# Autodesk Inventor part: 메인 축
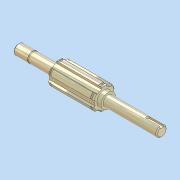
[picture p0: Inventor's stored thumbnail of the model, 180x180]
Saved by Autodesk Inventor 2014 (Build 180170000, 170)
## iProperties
Created: 2012-05
Part Number: 메인 축
Document SubType Name: 모델링
Designer: SeoGD™
Mass: 21.4461 g
Surface Area: 72.5104 cm^2
Volume: 21.4461 cm^3
Density: 1 g/cm^3
Material: 강철, 연강
Appearance: 강철
변환 표준: STEP AP214IS
파일 이름: C:\Users\SeoGD\Desktop\?쒗뿕\硫붿씤 異?.stp
전처리기: Build: 253, Release: 2010 SP1 - Date: Wed 07/29/2009
전송 단위: 밀리미터
불확실성: 0.01
Author: SeoGD™
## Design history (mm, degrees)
sketch "스케치1"
  geometry: L1 (-69.5, 0)-(69.5, 0); L2 (69.5, 0)-(69.5, 5); L3 (69.5, 5)-(55.5, 5); L4 (55.5, 5)-(55.5, 4.8); L5 (55.5, 4.8)-(54.35, 4.8); L6 (54.35, 4.8)-(54.35, 5); L7 (54.35, 5)-(30.5, 5); L8 (30.5, 5)-(30.5, 9); L9 (30.5, 9)-(-13.5, 9); L10 (-13.5, 9)-(-13.5, 7); L11 (-13.5, 7)-(-17.5, 7); L12 (-17.5, 7)-(-17.5, 5); L13 (-17.5, 5)-(-69.5, 5); L14 (-69.5, 5)-(-69.5, 0); 2 further points
  constraints: 28 end point, 9 parallel, 4 collinear, 2 perpendicular, 1 coincident, 1 horizontal, 1 midpoint
  dimensions: "d2" = 1.15 distance between parallel lines of L6 L4; "d3" = 10 diameter of L3 L1; "d4" = 9.6 diameter of L5 L1; "d6" = 44 distance between parallel lines of L10 L8; "d7" = 4 distance between parallel lines of L12 L10; "d8" = 14 diameter of L11 L1; "d9" = 18 diameter of L9 L1; "d33" = 52 distance from line of L12.end L14; "d37" = 39 distance between parallel lines of L8 L2; "d38" = 14 distance between parallel lines of L2 L4
revolve "회전1" sketch "스케치1" stored, may be unused: angle "d10" = 90 deg
sketch "스케치2"
  geometry: L1 (2.5, 10.712)-(2.5, 8.646); L2 (-2.5, 10.712)-(-2.5, 8.646); A1 r 9 centre (0, 0) between (2.5, 8.646) and (-2.5, 8.646) reference; A2 r 11 centre (0, 0) between (2.5, 10.712) and (-2.5, 10.712); 1 further point
  constraints: 4 end point, 4 point on circle, 2 parallel, 1 centre point, 1 coincident, 1 vertical
  dimensions: "d11" = 22 diameter of A2; "d12" = 5 distance between parallel lines of L1 L2
extrude "돌출1" join sketch "스케치2" stored distance "d13" = 10; taper "d14" = 0 deg
chamfer "모따기1" distance "d15" = 1; stored, may be unused: second distance "d16" = 2, angle "d17" = 45 deg
node "작업 평면1"
node "작업 평면2"
sketch "스케치3"
  geometry: L1 (2.5, 10.712)-(2.5, 10.198); L2 (-2.5, 10.712)-(-2.5, 10.198); A1 r 11 centre (0, 0) between (2.5, 10.712) and (-2.5, 10.712) reference; A2 r 10.5 centre (0, 0) between (2.5, 10.198) and (-2.5, 10.198); 1 further point
  constraints: 4 end point, 2 point on circle, 1 centre point, 1 coincident, 1 parallel, 1 vertical
  dimensions: "d19" = 21 diameter of A2
extrude "돌출2" cut sketch "스케치3" distance "d20" = 1.35; taper "d21" = 0 deg
node "작업 평면3"
sketch "스케치4"
  geometry: L1 (-26, -5)-(-26, 5) reference; L2 (-26, 1.5)-(-12.5, 1.5); L3 (-12.5, -1.5)-(-26, -1.5); A1 r 1.5 centre (-12.5, 0) between (-12.5, -1.5) and (-12.5, 1.5); 2 further points
  constraints: 4 end point, 2 perpendicular, 2 point on circle, 2 point on line, 2 tangent, 1 centre point, 1 horizontal alignment, 1 midpoint
  dimensions: "d25" = 3 distance between parallel lines of L3 L2; "d26" = 15 dimension on A1 L1
extrude "돌출3" cut sketch "스케치4" distance "d27" = 1.8; taper "d28" = 0 deg
chamfer "모따기2" distance "d29" = 1; stored, may be unused: second distance "d30" = 2, angle "d31" = 45 deg
node "솔리드1"
node "솔리드 본체"
node "곡면 본체"
mirror "대칭1"
pattern_circular "원형 패턴1" dims "d23" = 360 deg
node "솔리드2"
other parameters: "d18" = -1.65
